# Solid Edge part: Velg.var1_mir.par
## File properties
Author: jaanm
Template: Ansi Inch Part.par
Last saved by: jaanm
Revision: 2
Application: Solid Edge
Accuracy: 0,990
Username: jaanm
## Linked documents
Velg.var1.par
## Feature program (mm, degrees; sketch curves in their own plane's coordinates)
part copy "CopiedPart_1"
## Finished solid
Body 1: solid body, 77 faces, 180 edges, 89 vertices.
  Faces by surface: cylinder 40, plane 24, torus 12, cone 1
  Edges by curve: circle 81, line 68, intersection 30, curve on surface 1
Bounding box of the edges (mm; curved faces can reach further): 200.000 x 250.000 x 250.000, from (-108.955, -125, -158.5) to (91.045, 125, 91.5).
Cylindrical faces by radius (mm): R6.5 x7, R10 x17, R15 x1, R44.8943 x9, R79.6098 x5, R105 x1
Conical faces (half-angle, radius in mm at the cone's reference point): 0 deg R79.6098 x1
Toroidal faces (ring radius, tube radius in mm): R56.1241 r23.4857 x3, R89.6098 r10 x5, R99.375 r25.625 x2, R102.3049 r23.9455 x1, R106.5839 r6 x1
Planar faces by outward normal: +x 2, +z 2, -x 12, oblique 8
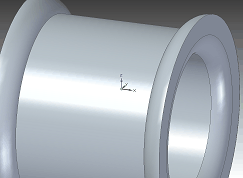
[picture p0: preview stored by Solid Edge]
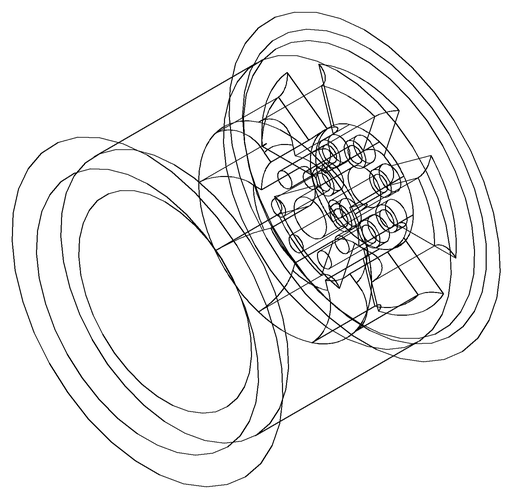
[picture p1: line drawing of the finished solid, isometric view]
